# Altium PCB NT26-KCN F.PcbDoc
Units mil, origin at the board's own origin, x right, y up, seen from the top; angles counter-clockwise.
Board outline 1222.67 x 1229.6 mil, 4 copper layers (Top Layer, GND1, Signal Layer 1, Bottom Layer), stack 29.559 mil thick; 1 components, 0 nets, 218 pads, 0 vias.
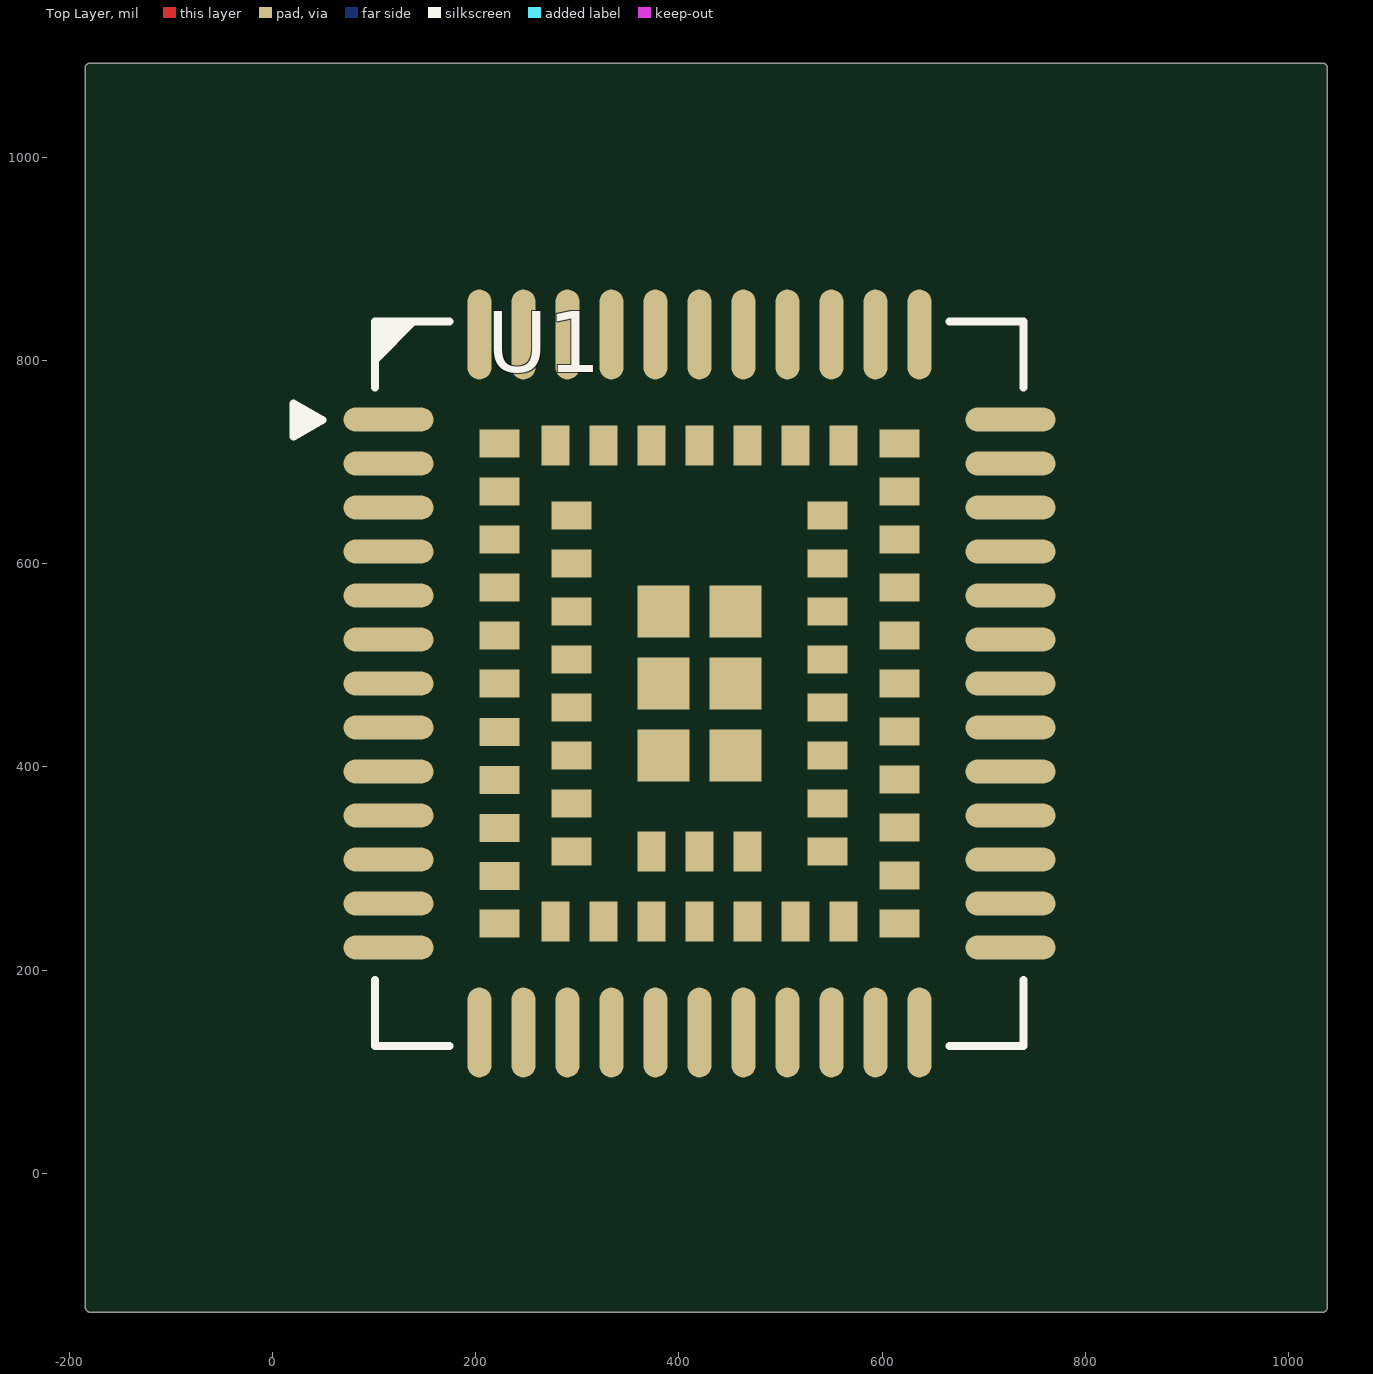
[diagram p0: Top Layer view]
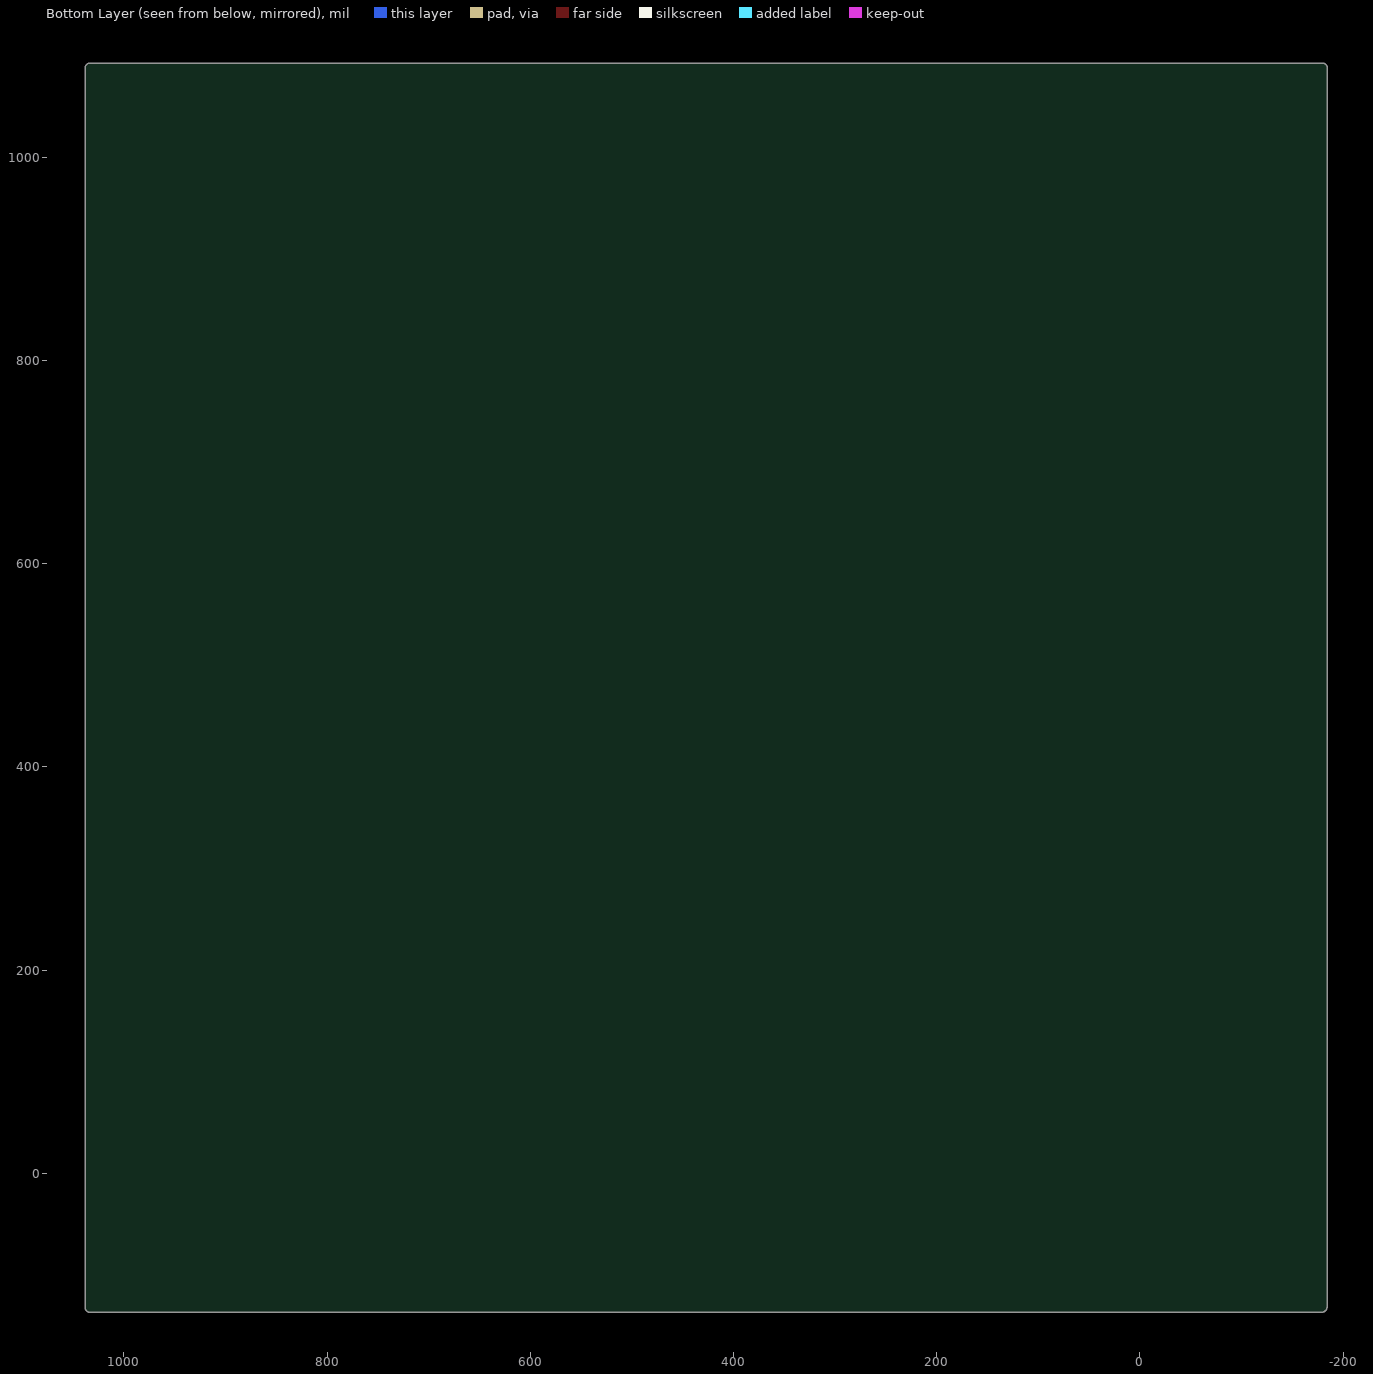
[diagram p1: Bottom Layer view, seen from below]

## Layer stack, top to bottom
Top Solder: solder mask 0.4, Solder Resist, Dk 3.5
Top Layer: signal copper 1
Dielectric1: core 2.9528, 1080, Dk 4.2
GND1: signal copper 0.9843
Dielectric2: core 19.685, 1080, Dk 4.2
Signal Layer 1: signal copper 0.9843
Dielectric 3: prepreg 2.9528, Dk 4.2
Bottom Layer: signal copper 1
Bottom Solder: solder mask 0.4, Solder Resist, Dk 3.5

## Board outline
-184.31,-131.54 -184.31,-123.37 cw(c-179.45,-122.13) -184.46,-122.13 -184.46,1087.68 cw(c-179.45,1087.68) -179.45,1092.69 1033.19,1092.69 cw(c1033.19,1087.68) 1038.2,1087.68 1038.2,-131.89 cw(c1033.19,-131.89) 1033.19,-136.9 -178.94,-136.9 cw(c-178.94,-131.89) -182.5,-135.42 -182.48,-135.44 -182.84,-135.08 -182.82,-135.1 cw(c-179.29,-131.54)

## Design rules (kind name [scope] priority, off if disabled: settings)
Clearance keepout [IsKeepOut] p1: gap=7.87 ignorepadtopadclearanceinfootprint=FALSE except(0: Arc-Arc Arc-Track Arc-SMDPad Arc-THPad Arc-Fill Arc-Poly Arc-Region Arc-Hole Track-Track Track-SMDPad Track-THPad Track-Fill Track-Poly Track-Region Track-Hole SMDPad-Hole THPad-Hole Via-Hole Fill-Hole Poly-Hole Region-Hole Text-Hole; 11.81: Arc-Via Track-Via)
Clearance Clearance_via [InDrillLayerPair('GND1 - Signal Layer 1') vs InDrillLayerPair('GND1 - Signal Layer 1')] p2: gap=5.91 ignorepadtopadclearanceinfootprint=TRUE
Clearance via [IsVia vs IsVia] p3: gap=5 ignorepadtopadclearanceinfootprint=FALSE except(4.2: Via-Via)
Clearance PAD&PAD [IsPad vs IsPad] p4: gap=7.87 ignorepadtopadclearanceinfootprint=TRUE
Clearance Clearance_50_TOP [InNetClass('Net Class_50') vs InNet('GND') And OnLayer('Top Layer')] p5: gap=3 ignorepadtopadclearanceinfootprint=TRUE except(0: Arc-Hole Track-Hole SMDPad-Hole THPad-Hole Via-Hole Fill-Hole Poly-Hole Region-Hole Text-Hole; 4.5: Arc-Fill Arc-Poly Arc-Region Track-Fill Track-Poly Track-Region SMDPad-Fill SMDPad-Poly SMDPad-Region THPad-Fill THPad-Poly THPad-Region Via-Fill Via-Poly Via-Region Fill-Fill Fill-Poly Fill-Region Poly-Poly Poly-Region Region-Region; 8: SMDPad-SMDPad)
Clearance Clearance_50_SIG [InNetClass('Net Class_50') vs InNet('GND') And OnLayer('Signal Layer 1')] p6: gap=3 ignorepadtopadclearanceinfootprint=TRUE except(0: Arc-Hole Track-Hole SMDPad-Hole THPad-Hole Via-Hole Fill-Hole Poly-Hole Region-Hole Text-Hole; 5: Arc-Fill Arc-Poly Arc-Region Track-Fill Track-Poly Track-Region SMDPad-Fill SMDPad-Poly SMDPad-Region THPad-Fill THPad-Poly THPad-Region Via-Fill Via-Poly Via-Region Fill-Fill Fill-Poly Fill-Region Poly-Poly Poly-Region Region-Region; 8: SMDPad-SMDPad)
Clearance Clearance_polygon [InPolygon] p7: gap=3 ignorepadtopadclearanceinfootprint=TRUE except(0: Arc-Hole Track-Hole SMDPad-Hole THPad-Hole Via-Hole Fill-Hole Poly-Hole Region-Hole Text-Hole; 5: Arc-Fill Arc-Poly Arc-Region Track-Fill Track-Poly Track-Region SMDPad-Fill SMDPad-Poly SMDPad-Region THPad-Fill THPad-Poly THPad-Region Via-Fill Via-Poly Via-Region Fill-Fill Fill-Poly Fill-Region Poly-Poly Poly-Region Region-Region; 8: SMDPad-SMDPad)
Clearance all [All] p8: gap=3 ignorepadtopadclearanceinfootprint=TRUE except(0: Arc-Hole Track-Hole SMDPad-Hole THPad-Hole Via-Hole Fill-Hole Poly-Hole Region-Hole Text-Hole; 4: Arc-Fill Arc-Poly Arc-Region Track-Fill Track-Poly Track-Region SMDPad-Fill SMDPad-Poly SMDPad-Region THPad-Fill THPad-Poly THPad-Region Via-Fill Via-Poly Via-Region Fill-Fill Fill-Poly Fill-Region Poly-Poly Poly-Region Region-Region; 8: SMDPad-SMDPad)
ComponentClearance [All] p1: gap=0 collisioncheckmode=3 verticalgap=0 showdistances=FALSE
DiffPairsRouting [All] p1: maxlimit=5 minlimit=5 mostfreqgap=5 toplayer_minwidth=3.25 toplayer_maxwidth=3.25 toplayer_prefwidth=3.25 midlayer1_minwidth=2.52 midlayer1_maxwidth=2.52 midlayer1_prefwidth=2.52 midlayer2_minwidth=2.52 midlayer2_maxwidth=2.52 midlayer2_prefwidth=2.52 bottomlayer_minwidth=3.25 bottomlayer_maxwidth=3.25 bottomlayer_prefwidth=3.25 maxuncoupledlength=500
HoleSize [All] p1: absolutevalues=TRUE maxlimit=196.85 minlimit=0 maxpercent=80.000 minpercent=20.000
HoleToHoleClearance [All] p1: gap=3 allowstackedmicrovias=TRUE
MinimumSolderMaskSliver [All] p1: minsoldermaskwidth=0
PolygonConnect [All] p1: connectstyle=Direct reliefconductorwidth=10 reliefentries=4 polygonreliefangle="90 Angle" airgapwidth=10
RoomDefinition "NT26-KCN F" [InComponentClass('NT26-KCN F')] p1: confinementstyle=ConfineIn formatcopy=TRUE lockcomponents=FALSE outline -12979.66,-8447.64 -10979.66,-8447.64 -10979.66,-7447.64 -12979.66,-7447.64
RoutingVias RoutingVias_1 [InDrillLayerPair('Top Layer - GND1')   OR InDrillLayerPair('Signal Layer 1 - Bottom Layer')] p1: holewidth=3.94 width=8.66 viastyle="Through Hole" minholewidth=3.94 minwidth=8.66 maxholewidth=11.81 maxwidth=19.68
RoutingVias [InDrillLayerPair('GND1 - Signal Layer 1')] p2: holewidth=7.87 width=13.78 viastyle="Through Hole" minholewidth=7.87 minwidth=13.78 maxholewidth=8.66 maxwidth=15.75
SilkToSilkClearance [All] p1: silktosilkclearance=0
SilkToSolderMaskClearance [IsPad] p1: minsilkscreentomaskgap=0 clearancetoexposedcopper=TRUE
SolderMaskExpansion [All] p1: expansion=4
Width 50 [InNetClass('Net Class_50')] p1: maxlimit=3.5 minlimit=3 preferedwidth=3.5 toplayer_minwidth=3.5 midlayer1_maxwidth=3 midlayer1_prefwidth=3 midlayer2_maxwidth=3 midlayer2_prefwidth=3 bottomlayer_minwidth=3.5 minimp=50.000000 maximp=50.000000 favimp=50.000000
Width [All] p2: maxlimit=196.85 minlimit=2.76 preferedwidth=2.99
23 further rules are at their usual default settings.

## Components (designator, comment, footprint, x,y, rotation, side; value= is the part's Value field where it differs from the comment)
U1 "NT26-KCN F" "NT26-KCN F" 420.2,481.93 r0 top

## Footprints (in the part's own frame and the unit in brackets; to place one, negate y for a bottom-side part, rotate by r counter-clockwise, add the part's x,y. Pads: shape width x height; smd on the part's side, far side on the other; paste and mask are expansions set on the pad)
"NT26-KCN F" [mm]
  oval 2.25x0.6 smd mask+0.102: 1(-7.775,6.6) 2(-7.775,5.5) 3(-7.775,4.4) 4(-7.775,3.3) 5(-7.775,2.2) 6(-7.775,1.1) 7(-7.775,0) 8(-7.775,-1.1) 9(-7.775,-2.2) 10(-7.775,-3.3) 11(-7.775,-4.4) 12(-7.775,-5.5) 13(-7.775,-6.6) 23(7.775,-6.6) 24(7.775,-5.5) 25(7.775,-4.4) 26(7.775,-3.3) 27(7.775,-2.2) 28(7.775,-1.1) 29(7.775,0) 30(7.775,1.1) 31(7.775,2.2) 32(7.775,3.3) 33(7.775,4.4) 34(7.775,5.5) 35(7.775,6.6)
  oval 0.6x2.25 smd mask+0.102: 14(-4.4,-8.725) 15(-3.3,-8.725) 16(-2.2,-8.725) 17(-1.1,-8.725) 18(0,-8.725) 19(1.1,-8.725) 20(2.2,-8.725) 21(3.3,-8.725) 22(4.4,-8.725) 36(4.4,8.725) 37(3.3,8.725) 38(2.2,8.725) 39(1.1,8.725) 40(0,8.725) 41(-1.1,8.725) 42(-2.2,8.725) 43(-3.3,8.725) 44(-4.4,8.725) 95(-5.5,-8.725) 96(5.5,-8.725) 97(5.5,8.725) 98(-5.5,8.725)
  rect 1x0.7 smd: 45(-5,4.8) 46(-5,3.6) 47(-5,2.4) 48(-5,1.2) 49(-5,0) 50(-5.003,-1.211) 51(-5.003,-2.411) 52(-5.003,-3.611) 53(-5.003,-4.811) 59(5,-4.8) 60(5,-3.6) 61(5,-2.4) 62(5,-1.2) 63(5,0) 64(5,1.2) 65(5,2.4) 66(5,3.6) 67(5,4.8) 73(-3.2,4.2) 74(-3.2,3) 75(-3.2,1.8) 76(-3.2,0.6) 77(-3.2,-0.6) 78(-3.2,-1.8) 79(-3.2,-3) 80(-3.2,-4.2) 81(3.2,-4.2) 82(3.2,-3) 83(3.2,-1.8) 84(3.2,-0.6) 85(3.2,0.6) 86(3.2,1.8) 87(3.2,3) 88(3.2,4.2) 99(-5,6) 100(-5,-6) 103(5,-6) 104(5,6)
  rect 0.7x1 smd: 54(-2.4,-5.95) 55(-1.2,-5.95) 56(0,-5.95) 57(1.2,-5.95) 58(2.4,-5.95) 68(2.4,5.95) 69(1.2,5.95) 70(0,5.95) 71(-1.2,5.95) 72(-2.4,5.95) 101(-3.6,-5.95) 102(3.6,-5.95) 105(3.6,5.95) 106(-3.6,5.95) 107(-1.2,-4.2) 108(0,-4.2) 109(1.2,-4.2)
  rect 1.3x1.3 smd: 89(-0.9,1.8) 90(-0.9,0) 91(-0.9,-1.8) 92(0.9,-1.8) 93(0.9,0) 94(0.9,1.8)
  oval 1.5x0.6 on Mech1 mask+0.076: ""(-7.4,-6.6) ""(-7.4,-5.5) ""(-7.4,-4.4) ""(-7.4,-3.3) ""(-7.4,-2.2) ""(-7.4,-1.1) ""(-7.4,0) ""(-7.4,1.1) ""(-7.4,2.2) ""(-7.4,3.3) ""(-7.4,4.4) ""(-7.4,5.5) ""(-7.4,6.6) ""(7.4,-6.6) ""(7.4,-5.5) ""(7.4,-4.4) ""(7.4,-3.3) ""(7.4,-2.2) ""(7.4,-1.1) ""(7.4,0) ""(7.4,1.1) ""(7.4,2.2) ""(7.4,3.3) ""(7.4,4.4) ""(7.4,5.5) ""(7.4,6.6)
  oval 0.6x1.5 on Mech1 mask+0.076: ""(-5.5,-8.35) ""(-5.5,8.35) ""(-4.4,-8.35) ""(-4.4,8.35) ""(-3.3,-8.35) ""(-3.3,8.35) ""(-2.2,-8.35) ""(-2.2,8.35) ""(-1.1,-8.35) ""(-1.1,8.35) ""(0,-8.35) ""(0,8.35) ""(1.1,-8.35) ""(1.1,8.35) ""(2.2,-8.35) ""(2.2,8.35) ""(3.3,-8.35) ""(3.3,8.35) ""(4.4,-8.35) ""(4.4,8.35) ""(5.5,-8.35) ""(5.5,8.35)
  rect 1x0.7 on Mech1: ""(-5.003,-4.811) ""(-5.003,-0.011) ""(-5.003,-3.611) ""(-5.003,-2.411) ""(-5.003,-1.211) ""(-5,-6) ""(-5,1.2) ""(-5,2.4) ""(-5,3.6) ""(-5,4.8) ""(-5,6) ""(-3.2,-4.2) ""(-3.2,-3) ""(-3.2,-1.8) ""(-3.2,-0.6) ""(-3.2,0.6) ""(-3.2,1.8) ""(-3.2,3) ""(-3.2,4.2) ""(3.2,-4.2) ""(3.2,-3) ""(3.2,-1.8) ""(3.2,-0.6) ""(3.2,0.6) ""(3.2,1.8) ""(3.2,3) ""(3.2,4.2) ""(5,-6) ""(5,-4.8) ""(5,-3.6) ""(5,-2.4) ""(5,0) ""(5,1.2) ""(5,2.4) ""(5,3.6) ""(5,4.8) ""(5,6) ""(5,-1.2)
  rect 0.7x1 on Mech1: ""(-3.6,-5.95) ""(-3.6,5.95) ""(-2.4,-5.95) ""(-2.4,5.95) ""(-1.2,-5.95) ""(-1.2,5.95) ""(0,-5.95) ""(0,5.95) ""(1.2,5.95) ""(1.2,-5.95) ""(2.4,-5.95) ""(2.4,5.95) ""(3.6,-5.95) ""(3.6,5.95)
  rrect30% 0.7x1 on Mech1: ""(-1.2,-4.2) ""(0,-4.2) ""(1.2,-4.2)
  rect 1.3x1.3 on Mech1: ""(-0.9,-1.8) ""(-0.9,0) ""(-0.9,1.8) ""(0.9,-1.8) ""(0.9,0) ""(0.9,1.8)
  silkscreen extent -10.14,-9.06 8.11,9.06

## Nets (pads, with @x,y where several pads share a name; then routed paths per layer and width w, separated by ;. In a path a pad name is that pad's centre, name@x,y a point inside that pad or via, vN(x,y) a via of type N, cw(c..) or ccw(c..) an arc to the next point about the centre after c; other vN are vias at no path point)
pads on no net: U1. U1.1 U1.2 U1.3 U1.4 U1.5 U1.6 U1.7 U1.8 U1.9 U1.10 U1.11 U1.12 U1.13 U1.14 U1.15 U1.16 U1.17 U1.18 U1.19 U1.20 U1.21 U1.22 U1.23 U1.24 U1.25 U1.26 U1.27 U1.28 U1.29 U1.30 U1.31 U1.32 U1.33 U1.34 U1.35 U1.36 U1.37 U1.38 U1.39 U1.40 U1.41 U1.42 U1.43 U1.44 U1.45 U1.46 U1.47 U1.48 U1.49 U1.50 U1.51 U1.52 U1.53 U1.54 U1.55 U1.56 U1.57 U1.58 U1.59 U1.60 U1.61 U1.62 U1.63 U1.64 U1.65 U1.66 U1.67 U1.68 U1.69 U1.70 U1.71 U1.72 U1.73 U1.74 U1.75 U1.76 U1.77 U1.78 U1.79 U1.80 U1.81 U1.82 U1.83 U1.84 U1.85 U1.86 U1.87 U1.88 U1.89 U1.90 U1.91 U1.92 U1.93 U1.94 U1.95 U1.96 U1.97 U1.98 U1.99 U1.100 U1.101 U1.102 U1.103 U1.104 U1.105 U1.106 U1.107 U1.108 U1.109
